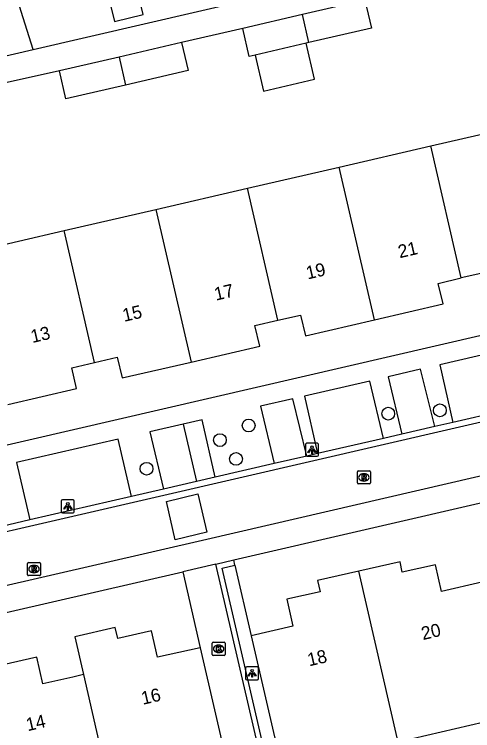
# Model space of a CAD drawing. Extents: x 156414 to 157775, y 382335 to 383765.
# Drawn here: x 156765.5 to 156800.6, y 382800.7 to 382855.5 of the extents above; entities that cross this region are included whole.
import ezdxf

# ---------------------------------------------------------------- set-up
doc = ezdxf.new("R2010")
doc.units = 0
for name, color, linetype in [('IMGEO_Boom', 7, 'Continuous'), ('IMGEO_Groenvoorziening', 7, 'Continuous'), ('IMGEO_Kolk', 7, 'Continuous'), ('IMGEO_Lichtpunt', 7, 'Continuous'), ('IMGEO_Muur', 7, 'Continuous'), ('IMGEO_Pand', 7, 'Continuous'), ('IMGEO_Pand_nummerreeks', 7, 'Continuous'), ('IMGEO_Parkeervlak_open', 7, 'Continuous'), ('IMGEO_Rijbaan_lokaal_gesloten', 7, 'Continuous'), ('IMGEO_Rijbaan_lokaal_open', 7, 'Continuous'), ('IMGEO_Rioolput', 7, 'Continuous'), ('IMGEO_Voetpad_open', 7, 'Continuous')]:
    doc.layers.add(name, color=color, linetype=linetype)

msp = doc.modelspace()

# ---------------------------------------------------------------- linework, layer by layer
at = {"layer": 'IMGEO_Boom'}
for centre in [(156794.167, 382824.928), (156798.117, 382825.181), (156783.483, 382824.023), (156781.278, 382822.903), (156782.515, 382821.465), (156775.662, 382820.71)]:
    msp.add_circle(centre, 0.489, dxfattribs=at)
at = {"layer": 'IMGEO_Groenvoorziening'}
msp.add_lwpolyline([(156782.43, 382813.341), (156783.681, 382807.923)], dxfattribs=at)
at = {"layer": 'IMGEO_Kolk'}
for p, q in [((156780.687, 382806.497), (156780.687, 382807.349)), ((156780.762, 382807.423), (156781.614, 382807.423)), ((156781.175, 382807.203), (156781.2, 382807.203)), ((156781.688, 382807.349), (156781.688, 382806.497)), ((156781.614, 382806.423), (156780.762, 382806.423)), ((156781.198, 382806.643), (156781.173, 382806.643))]:
    msp.add_line(p, q, dxfattribs=at)
for points in [[(156780.687, 382806.497), (156780.687, 382807.349)], [(156780.762, 382807.423), (156781.614, 382807.423)], [(156781.688, 382807.349), (156781.688, 382806.497)], [(156781.008, 382807.123), (156781.131, 382807.123), (156781.131, 382806.972), (156781.261, 382807.123), (156781.425, 382807.123), (156781.279, 382806.972), (156781.432, 382806.723), (156781.28, 382806.723), (156781.195, 382806.887), (156781.131, 382806.82), (156781.131, 382806.723), (156781.008, 382806.723), (156781.008, 382807.123)], [(156781.614, 382806.423), (156780.762, 382806.423)]]:
    msp.add_lwpolyline(points, dxfattribs=at)
for centre, start, end in [((156780.764, 382807.347), 91.552, 178.448), ((156780.764, 382807.347), 91.552, 178.448), ((156781.612, 382807.347), 1.552, 88.448), ((156781.612, 382807.347), 1.552, 88.448), ((156780.764, 382806.499), 181.552, 268.448), ((156780.764, 382806.499), 181.552, 268.448), ((156781.612, 382806.499), 271.552, 358.448), ((156781.612, 382806.499), 271.552, 358.448)]:
    msp.add_arc(centre, 0.0765, start, end, dxfattribs=at)
for centre, major_axis, ratio, start_param, end_param in [((156781.174, 382806.923), (-0.387, 0.002), 0.722429, 4.712389, 7.853982), ((156781.199, 382806.923), (-0.39, 0.002), 0.717154, 1.570796, 4.712389)]:
    msp.add_ellipse(centre, major_axis=major_axis, ratio=ratio, start_param=start_param, end_param=end_param, dxfattribs=at)
at = {"layer": 'IMGEO_Lichtpunt'}
for p, q in [((156787.832, 382822.564), (156787.832, 382821.757)), ((156787.832, 382822.564), (156787.832, 382821.757)), ((156788.734, 382822.659), (156787.926, 382822.659)), ((156788.734, 382822.659), (156787.926, 382822.659)), ((156788.828, 382821.757), (156788.828, 382822.564)), ((156788.828, 382821.757), (156788.828, 382822.564)), ((156787.926, 382821.663), (156788.734, 382821.663)), ((156787.926, 382821.663), (156788.734, 382821.663)), ((156769.136, 382818.231), (156769.136, 382817.424)), ((156769.136, 382818.231), (156769.136, 382817.424)), ((156770.038, 382818.326), (156769.23, 382818.326)), ((156770.038, 382818.326), (156769.23, 382818.326)), ((156770.132, 382817.424), (156770.132, 382818.231)), ((156770.132, 382817.424), (156770.132, 382818.231)), ((156769.23, 382817.33), (156770.038, 382817.33)), ((156769.23, 382817.33), (156770.038, 382817.33)), ((156783.243, 382805.451), (156783.243, 382804.644)), ((156783.243, 382805.451), (156783.243, 382804.644)), ((156784.145, 382805.546), (156783.337, 382805.546)), ((156784.145, 382805.546), (156783.337, 382805.546)), ((156784.239, 382804.644), (156784.239, 382805.451)), ((156784.239, 382804.644), (156784.239, 382805.451)), ((156783.337, 382804.55), (156784.145, 382804.55)), ((156783.337, 382804.55), (156784.145, 382804.55))]:
    msp.add_line(p, q, dxfattribs=at)
for points in [[(156788.206, 382822.228), (156788.245, 382822.2), (156788.057, 382821.938), (156788.019, 382821.965), (156788.206, 382822.228)], [(156788.308, 382822.18), (156788.355, 382822.18), (156788.355, 382821.858), (156788.308, 382821.858), (156788.308, 382822.18)], [(156788.418, 382822.2), (156788.456, 382822.227), (156788.643, 382821.965), (156788.604, 382821.937), (156788.418, 382822.2)], [(156769.51, 382817.895), (156769.549, 382817.867), (156769.361, 382817.605), (156769.323, 382817.632), (156769.51, 382817.895)], [(156769.612, 382817.847), (156769.659, 382817.847), (156769.659, 382817.525), (156769.612, 382817.525), (156769.612, 382817.847)], [(156769.722, 382817.867), (156769.76, 382817.894), (156769.947, 382817.632), (156769.908, 382817.604), (156769.722, 382817.867)], [(156783.617, 382805.115), (156783.656, 382805.087), (156783.468, 382804.825), (156783.43, 382804.852), (156783.617, 382805.115)], [(156783.719, 382805.067), (156783.766, 382805.067), (156783.766, 382804.745), (156783.719, 382804.745), (156783.719, 382805.067)], [(156783.829, 382805.087), (156783.867, 382805.114), (156784.054, 382804.852), (156784.015, 382804.824), (156783.829, 382805.087)]]:
    msp.add_lwpolyline(points, dxfattribs=at)
for centre in [(156788.331, 382822.362), (156769.635, 382818.029), (156783.742, 382805.249)]:
    msp.add_circle(centre, 0.0994, dxfattribs=at)
for centre, start, end in [((156787.926, 382822.564), 90, 180), ((156787.926, 382822.564), 90, 180), ((156788.734, 382822.564), 0, 90), ((156788.734, 382822.564), 0, 90), ((156787.926, 382821.757), 180, 270), ((156787.926, 382821.757), 180, 270), ((156788.734, 382821.757), 270, 0), ((156788.734, 382821.757), 270, 360), ((156769.23, 382818.231), 90, 180), ((156769.23, 382818.231), 90, 180), ((156770.038, 382818.231), 0, 90), ((156770.038, 382818.231), 0, 90), ((156769.23, 382817.424), 180, 270), ((156769.23, 382817.424), 180, 270), ((156770.038, 382817.424), 270, 0), ((156770.038, 382817.424), 270, 360), ((156783.337, 382805.451), 90, 180), ((156783.337, 382805.451), 90, 180), ((156784.145, 382805.451), 0, 90), ((156784.145, 382805.451), 0, 90), ((156783.337, 382804.644), 180, 270), ((156783.337, 382804.644), 180, 270), ((156784.145, 382804.644), 270, 0), ((156784.145, 382804.644), 270, 360)]:
    msp.add_arc(centre, 0.0946, start, end, dxfattribs=at)
at = {"layer": 'IMGEO_Muur'}
for points in [[(156780.962, 382813.412), (156782.34, 382813.73)], [(156787.72, 382784.234), (156780.962, 382813.412)], [(156789.002, 382784.941), (156788.02, 382784.714), (156781.442, 382813.112), (156782.43, 382813.341)], [(156782.43, 382813.341), (156782.34, 382813.73)]]:
    msp.add_lwpolyline(points, dxfattribs=at)
at = {"layer": 'IMGEO_Pand'}
for points in [[(156766.983, 382852.812), (156765.163, 382858.57), (156762.748, 382858.014)], [(156773.219, 382854.96), (156775.412, 382855.496), (156774.676, 382858.508), (156772.482, 382857.972), (156773.219, 382854.96)], [(156792.375, 382856.588), (156787.589, 382855.48)], [(156792.375, 382856.588), (156792.871, 382854.445), (156788.085, 382853.337)], [(156787.589, 382855.48), (156783.024, 382854.424)], [(156788.085, 382853.337), (156787.589, 382855.48)], [(156783.978, 382852.387), (156783.52, 382852.281), (156783.024, 382854.424)], [(156778.348, 382853.343), (156773.562, 382852.235)], [(156778.348, 382853.343), (156778.844, 382851.2), (156774.058, 382850.092)], [(156787.89, 382853.292), (156783.978, 382852.387)], [(156783.978, 382852.387), (156784.618, 382849.622), (156788.53, 382850.527), (156787.89, 382853.292)], [(156788.085, 382853.337), (156787.89, 382853.292)], [(156764.098, 382852.148), (156766.983, 382852.812)], [(156773.562, 382852.235), (156768.997, 382851.179)], [(156773.562, 382852.235), (156774.058, 382850.092)], [(156774.058, 382850.092), (156769.493, 382849.036), (156768.997, 382851.179)], [(156797.417, 382845.429), (156804.431, 382847.049)], [(156790.403, 382843.808), (156797.417, 382845.429)], [(156799.754, 382835.316), (156797.417, 382845.429)], [(156783.388, 382842.187), (156790.403, 382843.808)], [(156793.104, 382832.119), (156790.403, 382843.808)], [(156776.374, 382840.566), (156783.388, 382842.187)], [(156785.725, 382832.077), (156783.388, 382842.187)], [(156769.36, 382838.946), (156776.374, 382840.566)], [(156776.374, 382840.566), (156779.075, 382828.879)], [(156762.345, 382837.325), (156769.36, 382838.946)], [(156771.693, 382828.853), (156769.36, 382838.946)], [(156807.133, 382835.358), (156801.852, 382834.13), (156801.483, 382835.718), (156799.754, 382835.316)], [(156793.104, 382832.119), (156798.381, 382833.346), (156797.996, 382834.907), (156799.754, 382835.316)], [(156785.725, 382832.077), (156787.45, 382832.478), (156787.819, 382830.89), (156793.104, 382832.119)], [(156779.075, 382828.879), (156784.347, 382830.093), (156783.962, 382831.668), (156785.725, 382832.077)], [(156771.693, 382828.853), (156773.424, 382829.251), (156773.79, 382827.662), (156779.075, 382828.879)], [(156765.048, 382825.633), (156770.313, 382826.852), (156769.935, 382828.448), (156771.693, 382828.853)], [(156801.337, 382812.021), (156798.245, 382811.315), (156797.778, 382813.362), (156795.233, 382812.781), (156795.085, 382813.582), (156791.906, 382812.863)], [(156791.906, 382812.863), (156788.748, 382812.148), (156788.942, 382811.29), (156786.397, 382810.714), (156786.86, 382808.665), (156783.681, 382807.923)], [(156794.934, 382799.788), (156791.906, 382812.863)], [(156779.772, 382807.008), (156776.501, 382806.275), (156776.034, 382808.302), (156773.462, 382807.709), (156773.264, 382808.567), (156770.171, 382807.854), (156770.837, 382804.948)], [(156783.681, 382807.923), (156786.03, 382797.749)], [(156779.772, 382807.008), (156782.104, 382796.837)], [(156770.837, 382804.948), (156770.627, 382804.901), (156770.011, 382804.764), (156767.728, 382804.254), (156767.262, 382806.281), (156764.689, 382805.69), (156764.492, 382806.547), (156761.396, 382805.835), (156762.07, 382802.905)], [(156770.837, 382804.948), (156773.17, 382794.779)], [(156803.704, 382801.814), (156794.934, 382799.788)]]:
    msp.add_lwpolyline(points, dxfattribs=at)
at = {"layer": 'IMGEO_Parkeervlak_open'}
msp.add_lwpolyline([(156778.474, 382824.126), (156779.481, 382819.729)], dxfattribs=at)
at = {"layer": 'IMGEO_Rijbaan_lokaal_gesloten'}
for points in [[(156704.67, 382802.003), (156706.623, 382802.451), (156776.982, 382818.697), (156816.178, 382827.739), (156855.39, 382836.785), (156925.817, 382853.068)], [(156926.664, 382849.268), (156923.197, 382848.454), (156856.378, 382832.904), (156817.084, 382823.811), (156780.281, 382815.295), (156707.464, 382798.538)]]:
    msp.add_lwpolyline(points, dxfattribs=at)
at = {"layer": 'IMGEO_Rijbaan_lokaal_open'}
for points in [[(156806.603, 382825.994), (156799.105, 382824.262)], [(156799.105, 382824.262), (156797.723, 382823.943)], [(156797.723, 382823.943), (156795.212, 382823.363)], [(156795.212, 382823.363), (156793.807, 382823.039)], [(156793.807, 382823.039), (156788.741, 382821.868)], [(156787.934, 382821.682), (156785.424, 382821.102)], [(156788.741, 382821.868), (156787.934, 382821.682)], [(156785.424, 382821.102), (156780.925, 382820.063)], [(156780.925, 382820.063), (156779.481, 382819.729)], [(156779.481, 382819.729), (156776.96, 382819.147)], [(156776.96, 382819.147), (156774.52, 382818.584)], [(156780.274, 382815.845), (156777.858, 382815.266), (156777.194, 382818.202), (156779.591, 382818.789), (156780.274, 382815.845)], [(156774.52, 382818.584), (156766.74, 382816.788)], [(156766.74, 382816.788), (156762.858, 382815.891)]]:
    msp.add_lwpolyline(points, dxfattribs=at)
at = {"layer": 'IMGEO_Rioolput'}
for p, q in [((156791.8, 382819.622), (156791.8, 382820.474)), ((156791.875, 382820.548), (156792.727, 382820.548)), ((156792.801, 382820.474), (156792.801, 382819.622)), ((156792.288, 382820.328), (156792.313, 382820.328)), ((156792.727, 382819.548), (156791.875, 382819.548)), ((156792.311, 382819.768), (156792.286, 382819.768)), ((156766.55, 382812.601), (156766.55, 382813.453)), ((156766.625, 382813.527), (156767.477, 382813.527)), ((156767.038, 382813.307), (156767.063, 382813.307)), ((156767.551, 382813.453), (156767.551, 382812.601)), ((156767.061, 382812.747), (156767.036, 382812.747)), ((156767.477, 382812.527), (156766.625, 382812.527))]:
    msp.add_line(p, q, dxfattribs=at)
for points in [[(156791.8, 382819.622), (156791.8, 382820.474)], [(156791.875, 382820.548), (156792.727, 382820.548)], [(156792.801, 382820.474), (156792.801, 382819.622)], [(156792.389, 382820.246), (156792.137, 382820.248), (156792.137, 382819.848)], [(156792.137, 382819.848), (156792.261, 382819.848), (156792.261, 382820.01), (156792.272, 382820.01)], [(156792.315, 382820.167), (156792.261, 382820.167), (156792.261, 382820.086)], [(156792.261, 382820.086), (156792.313, 382820.086)], [(156792.319, 382819.981), (156792.39, 382819.848), (156792.53, 382819.848), (156792.465, 382819.974)], [(156792.727, 382819.548), (156791.875, 382819.548)], [(156766.55, 382812.601), (156766.55, 382813.453)], [(156766.625, 382813.527), (156767.477, 382813.527)], [(156767.551, 382813.453), (156767.551, 382812.601)], [(156767.139, 382813.225), (156766.887, 382813.227), (156766.887, 382812.827)], [(156766.887, 382812.827), (156767.011, 382812.827), (156767.011, 382812.989), (156767.022, 382812.989)], [(156767.065, 382813.146), (156767.011, 382813.146), (156767.011, 382813.065)], [(156767.011, 382813.065), (156767.063, 382813.065)], [(156767.069, 382812.96), (156767.14, 382812.827), (156767.28, 382812.827), (156767.215, 382812.953)], [(156767.477, 382812.527), (156766.625, 382812.527)]]:
    msp.add_lwpolyline(points, dxfattribs=at)
for centre, radius, start, end in [((156791.877, 382820.472), 0.0765, 91.552, 178.448), ((156791.877, 382820.472), 0.0765, 91.552, 178.448), ((156792.725, 382820.472), 0.0765, 1.552, 88.448), ((156792.725, 382820.472), 0.0765, 1.552, 88.448), ((156792.271, 382819.957), 0.0533, 26.0293, 88.6989), ((156792.297, 382820.275), 0.19, 274.7715, 282.9687), ((156792.321, 382820.071), 0.0964, 77.0061, 93.1865), ((156792.335, 382820.128), 0.0378, 276.6634, 79.6772), ((156792.388, 382820.136), 0.109, 350.3612, 89.416), ((156792.386, 382820.136), 0.112, 277.5842, 350.9817), ((156792.37, 382819.921), 0.108, 29.5134, 73.7905), ((156791.877, 382819.624), 0.0765, 181.552, 268.448), ((156791.877, 382819.624), 0.0765, 181.552, 268.448), ((156792.725, 382819.624), 0.0765, 271.552, 358.448), ((156792.725, 382819.624), 0.0765, 271.552, 358.448), ((156766.627, 382813.451), 0.0765, 91.552, 178.448), ((156766.627, 382813.451), 0.0765, 91.552, 178.448), ((156767.475, 382813.451), 0.0765, 1.552, 88.448), ((156767.475, 382813.451), 0.0765, 1.552, 88.448), ((156767.021, 382812.936), 0.0533, 26.0293, 88.6989), ((156767.047, 382813.254), 0.19, 274.7715, 282.9687), ((156767.071, 382813.05), 0.0964, 77.0061, 93.1865), ((156767.085, 382813.107), 0.0378, 276.6634, 79.6772), ((156767.138, 382813.115), 0.109, 350.3612, 89.416), ((156767.136, 382813.115), 0.112, 277.5842, 350.9817), ((156767.12, 382812.9), 0.108, 29.5134, 73.7905), ((156766.627, 382812.603), 0.0765, 181.552, 268.448), ((156766.627, 382812.603), 0.0765, 181.552, 268.448), ((156767.475, 382812.603), 0.0765, 271.552, 358.448), ((156767.475, 382812.603), 0.0765, 271.552, 358.448)]:
    msp.add_arc(centre, radius, start, end, dxfattribs=at)
for centre, major_axis, ratio, start_param, end_param in [((156792.287, 382820.048), (-0.387, 0.002), 0.722429, 4.712389, 7.853982), ((156792.312, 382820.048), (-0.39, 0.002), 0.717154, 1.570796, 4.712389), ((156767.037, 382813.027), (-0.387, 0.002), 0.722429, 4.712389, 7.853982), ((156767.062, 382813.027), (-0.39, 0.002), 0.717154, 1.570796, 4.712389)]:
    msp.add_ellipse(centre, major_axis=major_axis, ratio=ratio, start_param=start_param, end_param=end_param, dxfattribs=at)
at = {"layer": 'IMGEO_Voetpad_open'}
for points in [[(156766.983, 382852.812), (156839.709, 382869.642)], [(156783.024, 382854.424), (156778.348, 382853.343)], [(156768.997, 382851.179), (156764.29, 382850.124)], [(156726.991, 382813.763), (156728.366, 382814.072), (156850.038, 382842.208)], [(156806.603, 382825.994), (156805.602, 382830.395), (156798.115, 382828.665), (156799.105, 382824.262)], [(156782.34, 382813.73), (156852.727, 382829.996)], [(156797.723, 382823.943), (156796.646, 382828.325), (156794.17, 382827.753), (156795.212, 382823.363)], [(156793.807, 382823.039), (156792.76, 382827.427), (156787.751, 382826.269), (156788.741, 382821.868)], [(156787.934, 382821.682), (156786.851, 382826.062), (156784.394, 382825.494), (156785.424, 382821.102)], [(156780.925, 382820.063), (156779.921, 382824.46), (156778.474, 382824.126)], [(156778.474, 382824.126), (156775.92, 382823.536), (156776.96, 382819.147)], [(156774.52, 382818.584), (156773.482, 382822.972), (156765.72, 382821.179), (156766.74, 382816.788)], [(156780.962, 382813.412), (156778.432, 382812.831)], [(156707.908, 382796.596), (156778.432, 382812.831)], [(156778.432, 382812.831), (156779.772, 382807.008)]]:
    msp.add_lwpolyline(points, dxfattribs=at)

# ---------------------------------------------------------------- texts
at = {"layer": 'IMGEO_Pand_nummerreeks'}
for s, rotation, p in [('21', 13.0041, (156795.042, 382836.827)), ('19', 13.0041, (156787.996, 382835.2)), ('17', 13.0041, (156780.971, 382833.577)), ('15', 13.0041, (156773.946, 382831.955)), ('13', 13.0041, (156766.921, 382830.333)), ('20', 13.0048, (156796.818, 382807.59)), ('18', 13.0048, (156788.106, 382805.579)), ('16', 12.9202, (156775.381, 382802.635)), ('14', 12.9202, (156766.564, 382800.613))]:
    msp.add_text(s, height=1, rotation=rotation, dxfattribs=at).set_placement(p)

doc.saveas('drawing.dxf')
